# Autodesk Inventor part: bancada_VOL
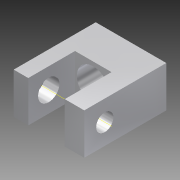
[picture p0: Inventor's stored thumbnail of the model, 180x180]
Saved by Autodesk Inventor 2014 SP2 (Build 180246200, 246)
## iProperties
Created: 2015-07
Part Number: bancada_VOL
Material: Acero
Document SubType Name: Modeling
Designer: Jaime
Appearance: Pulido - Pequeña pirámide Moleteado
Surface Area: 1644.79 cm^2
Volume: 1928.2 cm^3
Author: Jaime
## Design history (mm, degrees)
sketch "Boceto1"
  geometry: L1 (-92, -50)-(80, -50); L2 (80, -50)-(80, 50); L3 (80, 50)-(-92, 50); L4 (-92, 50)-(-92, -50); 1 further point
  constraints: 8 end point, 2 parallel, 1 horizontal, 1 perpendicular
  dimensions: "d0" = 92 distance from line of point (0, 0) L4; "d1" = 80 distance from line of L2 point (0, 0); "d2" = 100 distance between parallel lines of L1 L3; "d3" = 50 distance from line of L1 point (0, 0)
extrude "Extrusión1" new body sketch "Boceto1" distance "d4" = 150; taper "d6" = 0 deg; dims "d5" = 50, "d7" = 0
node "Punto de trabajo1"
  node "Eje de trabajo1"
hole "Hole1" diameter "d10" = 42; stored, may be unused: countersink angle "d14" = 90 deg, drill point angle "d16" = 118 deg; dims "d11" = 6, "d12" = 4, "d13" = 2, "d15" = 80, "d34" = 10, "d35" = 10
sketch "Boceto2"
  geometry: L1 (172, -200)-(0, -200) reference; L2 (35.5, -200)-(124.5, -200); L3 (124.5, -200)-(124.5, -86); L4 (124.5, -86)-(35.5, -86); L5 (35.5, -86)-(35.5, -200); L6 (35.5, -200)-(124.5, -86); L7 (124.5, -200)-(35.5, -86); 3 further points
  constraints: 12 end point, 3 midpoint, 2 parallel, 1 horizontal, 1 perpendicular, 1 vertical alignment
  dimensions: "d17" = 0 distance between parallel lines of L1 L2; "d18" = 89 distance of L3.end L4.end; "d22" = 64 distance from line of L4 point (80, -150)
extrude "Extrusión2" cut sketch "Boceto2" stored distance "d20" = 89 (= d18); taper "d21" = 0 deg
node "Punto de trabajo2"
  node "Eje de trabajo2"
hole "Hole2" diameter "d25" = 80; stored, may be unused: countersink angle "d29" = 90 deg, drill point angle "d31" = 0 deg; dims "d26" = 6, "d27" = 4, "d28" = 2, "d30" = 8, "d32" = 10, "d33" = 10
node "Punto de trabajo3"
  node "Eje de trabajo3"
hole "Hole3" diameter "d38" = 52; stored, may be unused: countersink angle "d42" = 90 deg, drill point angle "d44" = 118 deg; dims "d36" = 10, "d37" = 10, "d39" = 6, "d40" = 4, "d41" = 2, "d43" = 8
node "Sólido1"
